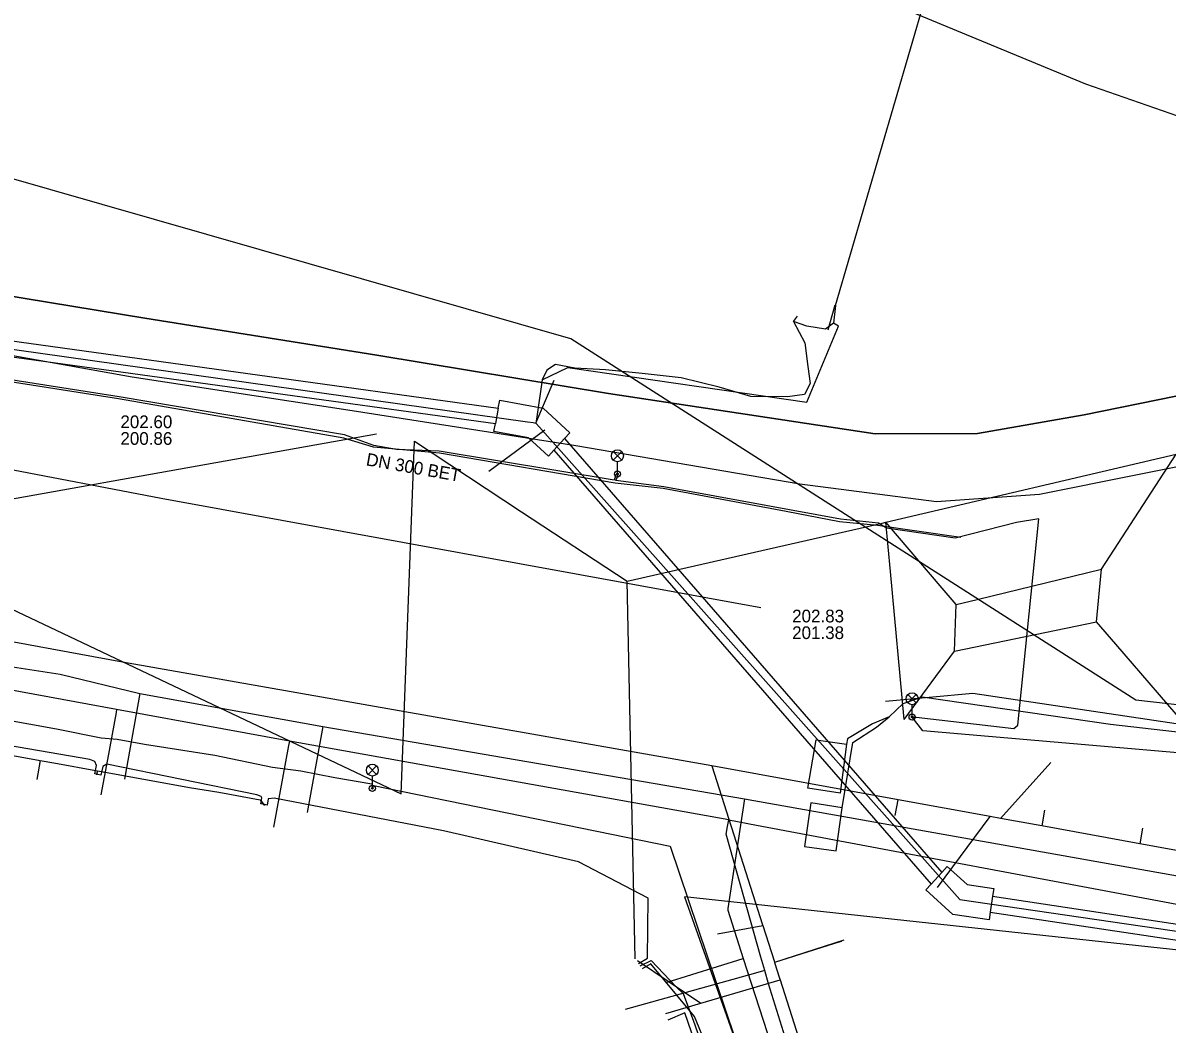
# Model space of a CAD drawing. Extents: x -596228 to -595156, y -1161235 to -1159373.
# Drawn here: x -595841.1 to -595769, y -1160360.2 to -1160297.1 of the extents above; entities that cross this region are included whole.
import ezdxf

# ---------------------------------------------------------------- set-up
doc = ezdxf.new("R2010")
doc.units = 0
for name, color, linetype in [('Vrstva 1', 7, 'Continuous'), ('Vrstva 10', 7, 'Continuous'), ('Vrstva 12', 7, 'Continuous'), ('Vrstva 14', 7, 'Continuous'), ('Vrstva 16', 7, 'Continuous'), ('Vrstva 33', 7, 'Continuous'), ('Vrstva 4', 7, 'Continuous'), ('Vrstva 42', 7, 'Continuous'), ('Vrstva 54', 7, 'Continuous'), ('Vrstva 55', 7, 'Continuous'), ('Vrstva 58', 7, 'Continuous'), ('Vrstva 9', 7, 'Continuous')]:
    doc.layers.add(name, color=color, linetype=linetype)

msp = doc.modelspace()

# ---------------------------------------------------------------- linework, layer by layer
at = {"layer": 'Vrstva 1'}
for p, q in [((-595806.58, -1160316.98), (-595854.43, -1160303.29)), ((-595832.393, -1160327.051), (-595871.84, -1160319.47)), ((-595832.39, -1160327.05), (-595871.84, -1160319.47)), ((-595794.593, -1160333.931), (-595832.39, -1160327.05)), ((-595794.59, -1160333.93), (-595832.39, -1160327.05)), ((-595776.32, -1160343.68), (-595779.499, -1160347.202)), ((-595786.122, -1160347.012), (-595785.943, -1160346.028)), ((-595776.709, -1160346.693), (-595776.888, -1160347.677)), ((-595783.46, -1160351.56), (-595780.139, -1160347.085)), ((-595770.541, -1160347.816), (-595770.72, -1160348.8)), ((-595797.33, -1160354.48), (-595794.477, -1160353.949)), ((-595797.328, -1160354.476), (-595794.48, -1160353.95)), ((-595789.37, -1160354.88), (-595793.729, -1160356.29)), ((-595802.38, -1160356.15), (-595798.38, -1160358.85))]:
    msp.add_line(p, q, dxfattribs=at)
for points in [[(-595760, -1160341), (-595761.123, -1160340.872), (-595770.963, -1160339.746), (-595806.58, -1160316.98)], [(-595765.83, -1160349.69), (-595770.72, -1160348.8), (-595776.888, -1160347.677), (-595779.499, -1160347.202), (-595780.139, -1160347.085), (-595785.943, -1160346.028), (-595797.69, -1160343.89)], [(-595789.506, -1160354.95), (-595789.956, -1160355.081), (-595793.729, -1160356.29)]]:
    msp.add_lwpolyline(points, dxfattribs=at)
at = {"layer": 'Vrstva 10'}
for p, q in [((-595887.89, -1160310.72), (-595811.15, -1160321.35)), ((-595887.89, -1160310.72), (-595811.15, -1160321.35)), ((-595888.05, -1160311.71), (-595811.33, -1160322.33)), ((-595888.05, -1160311.71), (-595811.33, -1160322.33)), ((-595811.15, -1160321.35), (-595811.33, -1160322.33)), ((-595811.15, -1160321.35), (-595811.33, -1160322.33)), ((-595806.97, -1160323.27), (-595807.64, -1160324.01)), ((-595806.97, -1160323.27), (-595807.64, -1160324.01)), ((-595806.97, -1160323.27), (-595783.19, -1160350.6)), ((-595806.97, -1160323.27), (-595783.19, -1160350.6)), ((-595807.64, -1160324.01), (-595783.86, -1160351.34)), ((-595807.64, -1160324.01), (-595783.86, -1160351.34)), ((-595783.19, -1160350.6), (-595783.86, -1160351.34)), ((-595783.19, -1160350.6), (-595783.86, -1160351.34)), ((-595779.99, -1160352.11), (-595780.14, -1160353.1)), ((-595779.99, -1160352.11), (-595780.14, -1160353.1)), ((-595779.99, -1160352.11), (-595735.23, -1160358.87)), ((-595779.99, -1160352.11), (-595735.23, -1160358.87)), ((-595780.14, -1160353.1), (-595735.26, -1160359.88)), ((-595780.14, -1160353.1), (-595735.26, -1160359.88))]:
    msp.add_line(p, q, dxfattribs=at)
for points in [[(-595811.15, -1160321.35), (-595811.06, -1160320.86), (-595808.32, -1160321.36), (-595806.63, -1160322.9), (-595806.97, -1160323.27)], [(-595811.15, -1160321.35), (-595811.06, -1160320.86), (-595808.32, -1160321.36), (-595806.63, -1160322.9), (-595806.97, -1160323.27)], [(-595807.64, -1160324.01), (-595807.98, -1160324.38), (-595809.25, -1160323.23), (-595811.42, -1160322.82), (-595811.33, -1160322.33)], [(-595807.64, -1160324.01), (-595807.98, -1160324.38), (-595809.25, -1160323.23), (-595811.42, -1160322.82), (-595811.33, -1160322.33)], [(-595783.19, -1160350.6), (-595782.85, -1160350.23), (-595781.6, -1160351.37), (-595779.92, -1160351.61), (-595779.99, -1160352.11)], [(-595783.19, -1160350.6), (-595782.85, -1160350.23), (-595781.6, -1160351.37), (-595779.92, -1160351.61), (-595779.99, -1160352.11)], [(-595780.14, -1160353.1), (-595780.21, -1160353.59), (-595782.49, -1160353.26), (-595784.2, -1160351.71), (-595783.86, -1160351.34)], [(-595780.14, -1160353.1), (-595780.21, -1160353.59), (-595782.49, -1160353.26), (-595784.2, -1160351.71), (-595783.86, -1160351.34)]]:
    msp.add_lwpolyline(points, dxfattribs=at)
at = {"layer": 'Vrstva 12'}
for p, q in [((-595789.89, -1160314.88), (-595777.93, -1160273.94)), ((-595790.362, -1160316.409), (-595789.904, -1160314.845)), ((-595789.89, -1160314.88), (-595790.02, -1160315.99)), ((-595792.54, -1160315.89), (-595792.28, -1160315.55)), ((-595789.7, -1160316.19), (-595790.02, -1160315.99)), ((-595808.78, -1160322.29), (-595807.62, -1160319.58)), ((-595811.75, -1160325.33), (-595808.21, -1160322.72)), ((-595809.314, -1160322.217), (-595808.956, -1160322.265)), ((-595808.956, -1160322.265), (-595808.78, -1160322.29)), ((-595808.78, -1160322.29), (-595808.547, -1160322.55)), ((-595840.02, -1160343.56), (-595840.06, -1160343.77)), ((-595836.4, -1160344.21), (-595836.47, -1160344.42))]:
    msp.add_line(p, q, dxfattribs=at)
for points in [[(-595930.09, -1160299.24), (-595889.94, -1160310.85), (-595809.314, -1160322.217)], [(-595792.54, -1160315.89), (-595791.83, -1160317.23), (-595791.63, -1160318.73), (-595791.48, -1160319.81), (-595791.84, -1160320.5), (-595792.92, -1160320.64), (-595795.22, -1160320.62), (-595797.23, -1160320.04), (-595799.61, -1160319.44), (-595802.07, -1160319.16), (-595804.38, -1160318.93), (-595806.33, -1160318.84), (-595807.54, -1160318.61), (-595808.09, -1160318.97), (-595808.38, -1160319.56)], [(-595808.38, -1160319.56), (-595806.76, -1160318.8), (-595791.7, -1160320.98), (-595789.7, -1160316.19)], [(-595790.02, -1160315.99), (-595790.52, -1160316.37), (-595791.69, -1160316.19), (-595792.54, -1160315.89)], [(-595808.38, -1160319.56), (-595808.719, -1160321.896), (-595808.78, -1160322.29)], [(-595808.547, -1160322.55), (-595782.05, -1160352.31), (-595733.28, -1160359.44)], [(-595858.15, -1160340.11), (-595856.31, -1160340.7), (-595850.28, -1160341.68), (-595840.02, -1160343.56)], [(-595840.02, -1160343.56), (-595839.17, -1160343.71), (-595836.4, -1160344.21)], [(-595836.4, -1160344.21), (-595835.57, -1160344.36), (-595830.62, -1160345.26), (-595828.76, -1160345.54), (-595826.15, -1160346.04), (-595825.94, -1160346.32)], [(-595797.48, -1160364.09), (-595797.91, -1160363.72), (-595799.39, -1160359.46), (-595800.47, -1160359.91)]]:
    msp.add_lwpolyline(points, dxfattribs=at)
at = {"layer": 'Vrstva 14'}
for p, q in [((-595796.71, -1160347.71), (-595796.62, -1160347.3)), ((-595796.62, -1160347.3), (-595794.88, -1160347.62)), ((-595794.88, -1160347.62), (-595751.09, -1160355.87))]:
    msp.add_line(p, q, dxfattribs=at)
for points in [[(-595796.62, -1160347.3), (-595824.314, -1160342.334), (-595828.542, -1160341.559), (-595835.203, -1160340.338), (-595848.129, -1160337.968), (-595856.324, -1160336.466), (-595859.13, -1160335.952), (-595871.786, -1160333.632), (-595881.289, -1160331.89), (-595903.564, -1160327.806)], [(-595835.203, -1160340.338), (-595835.24, -1160340.535), (-595835.782, -1160343.496), (-595836.19, -1160345.721)], [(-595824.314, -1160342.334), (-595824.366, -1160342.617), (-595825.307, -1160347.751)], [(-595779.99, -1160397.64), (-595780.18, -1160397.54), (-595780.72, -1160397.28), (-595782.55, -1160395.85), (-595783.69, -1160391.99), (-595785.31, -1160386.2), (-595787, -1160380.5), (-595787.925, -1160377.543), (-595788.79, -1160374.78), (-595790.115, -1160370.513), (-595792.33, -1160363.34), (-595794.11, -1160357.63), (-595794.351, -1160356.78), (-595794.59, -1160355.94), (-595796.79, -1160348.19), (-595796.71, -1160347.71)], [(-595794.351, -1160356.78), (-595794.495, -1160356.821), (-595795.457, -1160357.095), (-595803.151, -1160359.249)]]:
    msp.add_lwpolyline(points, dxfattribs=at)
at = {"layer": 'Vrstva 16'}
for p, q in [((-595833.73, -1160339.33), (-595834.7, -1160344.74)), ((-595822.21, -1160341.41), (-595823.19, -1160346.82)), ((-595800.57, -1160357.54), (-595795.71, -1160356.02))]:
    msp.add_line(p, q, dxfattribs=at)
for points in [[(-595846.15, -1160336.98), (-595838.77, -1160338.11), (-595833.73, -1160339.33), (-595822.21, -1160341.41), (-595795.62, -1160345.96), (-595752.4, -1160353.65), (-595705.45, -1160352.2), (-595699.2, -1160353.46), (-595687.59, -1160351.18), (-595687.183, -1160350.999), (-595649.82, -1160334.37), (-595637.18, -1160329.71), (-595632.58, -1160328.19), (-595631.22, -1160327.8), (-595629.94, -1160327.43), (-595628.67, -1160326.89), (-595623.45, -1160328.11), (-595616.75, -1160330.26), (-595616.2, -1160330.11), (-595541.13, -1160299.69), (-595536.93, -1160298.59)], [(-595795.62, -1160345.96), (-595796.67, -1160352.88), (-595796.68, -1160352.98)], [(-595796.68, -1160352.98), (-595795.71, -1160356.02), (-595792.44, -1160366.14), (-595787.82, -1160380.41), (-595782.96, -1160397.81)]]:
    msp.add_lwpolyline(points, dxfattribs=at)
at = {"layer": 'Vrstva 33'}
for p, q in [((-595803.9, -1160324.091), (-595803.37, -1160324.621)), ((-595803.9, -1160324.621), (-595803.37, -1160324.091)), ((-595803.635, -1160325.506), (-595803.635, -1160324.731)), ((-595785.329, -1160339.397), (-595784.799, -1160339.927)), ((-595785.329, -1160339.927), (-595784.799, -1160339.397)), ((-595785.064, -1160340.812), (-595785.064, -1160340.037)), ((-595819.35, -1160343.896), (-595818.82, -1160344.426)), ((-595819.35, -1160344.426), (-595818.82, -1160343.896)), ((-595819.085, -1160345.311), (-595819.085, -1160344.536))]:
    msp.add_line(p, q, dxfattribs=at)
for centre, radius in [((-595803.635, -1160324.356), 0.375), ((-595803.635, -1160325.506), 0.19), ((-595803.635, -1160325.506), 0.05), ((-595785.064, -1160339.662), 0.375), ((-595785.064, -1160340.812), 0.19), ((-595785.064, -1160340.812), 0.05), ((-595819.085, -1160344.161), 0.375), ((-595819.085, -1160345.311), 0.19), ((-595819.085, -1160345.311), 0.05)]:
    msp.add_circle(centre, radius, dxfattribs=at)
at = {"layer": 'Vrstva 42'}
for points in [[(-595847.13, -1160313.44), (-595833.42, -1160315.69), (-595818.81, -1160318.02), (-595804.19, -1160320.42), (-595787.39, -1160322.98), (-595780.95, -1160322.96), (-595774.21, -1160321.77), (-595762.67, -1160319.43), (-595752.552, -1160316.857), (-595741.43, -1160313.41), (-595738.39, -1160315.27), (-595735.13, -1160315.87), (-595731.62, -1160314.9), (-595724.29, -1160311.87), (-595722.868, -1160311.197), (-595714.82, -1160307.83), (-595703.02, -1160300.19), (-595693.78, -1160291.95), (-595681.58, -1160277.83), (-595677.955, -1160273.423), (-595678.45, -1160273.05)], [(-595847.13, -1160313.44), (-595833.42, -1160315.69), (-595818.81, -1160318.02), (-595804.19, -1160320.42), (-595787.39, -1160322.98), (-595780.95, -1160322.96), (-595774.21, -1160321.77), (-595762.67, -1160319.43), (-595752.552, -1160316.857), (-595741.43, -1160313.41), (-595738.39, -1160315.27), (-595735.13, -1160315.87), (-595731.62, -1160314.9), (-595724.29, -1160311.87), (-595722.868, -1160311.197), (-595714.82, -1160307.83), (-595703.02, -1160300.19), (-595693.78, -1160291.95), (-595681.58, -1160277.83), (-595677.955, -1160273.423), (-595678.45, -1160273.05)], [(-595678.45, -1160273.05), (-595677.955, -1160273.423), (-595681.58, -1160277.83), (-595693.78, -1160291.95), (-595703.02, -1160300.19), (-595714.82, -1160307.83), (-595722.868, -1160311.197), (-595724.29, -1160311.87), (-595731.62, -1160314.9), (-595735.13, -1160315.87), (-595738.39, -1160315.27), (-595741.43, -1160313.41), (-595752.552, -1160316.857), (-595762.67, -1160319.43), (-595774.21, -1160321.77), (-595780.95, -1160322.96), (-595787.39, -1160322.98), (-595804.19, -1160320.42), (-595818.81, -1160318.02), (-595833.42, -1160315.69), (-595847.13, -1160313.44)], [(-595847.13, -1160313.44), (-595833.42, -1160315.69), (-595818.81, -1160318.02), (-595804.19, -1160320.42), (-595787.39, -1160322.98), (-595780.95, -1160322.96), (-595774.21, -1160321.77), (-595762.67, -1160319.43), (-595752.552, -1160316.857), (-595741.43, -1160313.41), (-595738.39, -1160315.27), (-595735.13, -1160315.87), (-595731.62, -1160314.9), (-595724.29, -1160311.87), (-595722.868, -1160311.197), (-595714.82, -1160307.83), (-595703.02, -1160300.19), (-595693.78, -1160291.95), (-595681.58, -1160277.83), (-595677.955, -1160273.423)], [(-595847.13, -1160313.44), (-595833.42, -1160315.69), (-595818.81, -1160318.02), (-595804.19, -1160320.42), (-595787.39, -1160322.98), (-595780.95, -1160322.96), (-595774.21, -1160321.77), (-595762.67, -1160319.43), (-595752.552, -1160316.857), (-595741.43, -1160313.41), (-595738.39, -1160315.27), (-595735.13, -1160315.87), (-595731.62, -1160314.9), (-595724.29, -1160311.87), (-595722.868, -1160311.197), (-595714.82, -1160307.83), (-595703.02, -1160300.19), (-595693.78, -1160291.95), (-595681.58, -1160277.83), (-595677.955, -1160273.423)], [(-595847.13, -1160313.44), (-595833.42, -1160315.69), (-595818.81, -1160318.02), (-595804.19, -1160320.42), (-595787.39, -1160322.98), (-595780.95, -1160322.96), (-595774.21, -1160321.77), (-595762.67, -1160319.43), (-595752.552, -1160316.857), (-595741.43, -1160313.41), (-595738.39, -1160315.27), (-595735.13, -1160315.87), (-595731.62, -1160314.9), (-595724.29, -1160311.87), (-595722.868, -1160311.197), (-595714.82, -1160307.83), (-595703.02, -1160300.19), (-595693.78, -1160291.95), (-595681.58, -1160277.83), (-595677.955, -1160273.423)], [(-595847.13, -1160313.44), (-595833.42, -1160315.69), (-595818.81, -1160318.02), (-595804.19, -1160320.42), (-595787.39, -1160322.98), (-595780.95, -1160322.96), (-595774.21, -1160321.77), (-595762.67, -1160319.43), (-595752.552, -1160316.857), (-595741.43, -1160313.41), (-595738.39, -1160315.27), (-595735.13, -1160315.87), (-595731.62, -1160314.9), (-595724.29, -1160311.87), (-595722.868, -1160311.197), (-595714.82, -1160307.83), (-595703.02, -1160300.19), (-595693.78, -1160291.95), (-595681.58, -1160277.83), (-595677.955, -1160273.423)], [(-595895.894, -1160304.949), (-595895.931, -1160305.565), (-595896.41, -1160308.706), (-595893.65, -1160309.078), (-595880.587, -1160311.231), (-595867.748, -1160313.527), (-595860.217, -1160314.981), (-595847.991, -1160316.922), (-595834.216, -1160319.371), (-595820.364, -1160321.5), (-595806.264, -1160323.708), (-595792.142, -1160326.114), (-595783.529, -1160327.233), (-595777.032, -1160326.773), (-595764.779, -1160324.315), (-595754.282, -1160321.569), (-595753.606, -1160323.921), (-595750.637, -1160332.868), (-595750.632, -1160333.38), (-595740.462, -1160333.548), (-595739.673, -1160332.748), (-595739.749, -1160331.939)], [(-595786.51, -1160340.81), (-595785.62, -1160339.97), (-595784.43, -1160339.54), (-595772.55, -1160341.27), (-595759.72, -1160342.74), (-595753.29, -1160343.01), (-595746.78, -1160343.15), (-595744.71, -1160344.54), (-595744.9, -1160333.41), (-595739.78, -1160333.4), (-595731.42, -1160332.67), (-595721.4, -1160331.47), (-595721.02, -1160331.89), (-595720.93, -1160332.76), (-595720.32, -1160336.61), (-595718.38, -1160336.3), (-595717.93, -1160338.83), (-595719.88, -1160339.16), (-595720.32, -1160336.61)], [(-595756.32, -1160342.9), (-595757.1, -1160342.84), (-595759.12, -1160342.98), (-595766.45, -1160341.54), (-595781.24, -1160339.33), (-595786.74, -1160339.83)], [(-595789.47, -1160346.54), (-595791.44, -1160346.22), (-595791.85, -1160348.97), (-595789.86, -1160349.24), (-595789.47, -1160346.54), (-595788.79, -1160342.41), (-595787.31, -1160341.45), (-595786.51, -1160340.81), (-595787.57, -1160341.25), (-595789.13, -1160342.19), (-595789.19, -1160342.53), (-595789.6, -1160345.62), (-595791.63, -1160345.3), (-595791.12, -1160342.26), (-595789.19, -1160342.53)], [(-595802.315, -1160356.348), (-595801.748, -1160356.007), (-595801.706, -1160352.231), (-595806.091, -1160349.948), (-595814.606, -1160347.981), (-595825.263, -1160345.929), (-595825.632, -1160345.967), (-595825.653, -1160345.979), (-595825.707, -1160346.367), (-595825.893, -1160346.33), (-595826.107, -1160346.291), (-595826.046, -1160345.903), (-595826.096, -1160345.815), (-595826.364, -1160345.707), (-595835.813, -1160343.79), (-595836.08, -1160343.929), (-595836.193, -1160344.469), (-595836.392, -1160344.434), (-595836.583, -1160344.396), (-595836.47, -1160343.865), (-595836.579, -1160343.616), (-595836.883, -1160343.496), (-595845.341, -1160342.033)], [(-595802.213, -1160356.494), (-595801.501, -1160356.155), (-595799.925, -1160357.815), (-595799.472, -1160358.259)], [(-595788.218, -1160395.186), (-595787.922, -1160394.034), (-595788.748, -1160391.473), (-595790.389, -1160386.386), (-595791.885, -1160381.611), (-595792.977, -1160378.739), (-595793.48, -1160376.711), (-595793.46, -1160376.649), (-595793.33, -1160376.236), (-595793.283, -1160375.424), (-595794.728, -1160370.765), (-595796.979, -1160363.921), (-595797.998, -1160361.576), (-595798.784, -1160359.683), (-595799.078, -1160359.328), (-595801.526, -1160356.363), (-595802.086, -1160356.676)], [(-595793.939, -1160376.733), (-595794.104, -1160376.213), (-595793.629, -1160376.048), (-595793.665, -1160375.597), (-595795.975, -1160367.94), (-595796.283, -1160367.628), (-595796.85, -1160367.774), (-595796.901, -1160367.605), (-595796.969, -1160367.392), (-595796.392, -1160367.161), (-595796.411, -1160366.856), (-595798.853, -1160359.936), (-595799.078, -1160359.328), (-595799.472, -1160358.259)]]:
    msp.add_lwpolyline(points, dxfattribs=at)
at = {"layer": 'Vrstva 54'}
for p, q in [((-595818.83, -1160322.99), (-595829.53, -1160324.9)), ((-595816.56, -1160326.77), (-595816.43, -1160323.44)), ((-595816.43, -1160323.44), (-595809.68, -1160327.88)), ((-595786.71, -1160328.54), (-595768.42, -1160324.25)), ((-595773.12, -1160331.49), (-595768.42, -1160324.25)), ((-595829.53, -1160324.9), (-595847.48, -1160328.1)), ((-595817.27, -1160345.66), (-595816.56, -1160326.77)), ((-595809.68, -1160327.88), (-595803.02, -1160332.26)), ((-595794.54, -1160330.33), (-595786.95, -1160328.59)), ((-595786.95, -1160328.59), (-595786.71, -1160328.54)), ((-595786.42, -1160331.64), (-595786.71, -1160328.54)), ((-595783.17, -1160332.69), (-595786.71, -1160328.54)), ((-595803.02, -1160332.26), (-595794.54, -1160330.33)), ((-595848.051, -1160331.075), (-595817.27, -1160345.66)), ((-595780.96, -1160333.41), (-595773.12, -1160331.49)), ((-595773.444, -1160334.821), (-595773.12, -1160331.49)), ((-595802.51, -1160356.06), (-595803.02, -1160332.26)), ((-595785.56, -1160340.96), (-595786.42, -1160331.64)), ((-595782.28, -1160333.73), (-595783.17, -1160332.69)), ((-595782.402, -1160336.659), (-595782.28, -1160333.73)), ((-595782.28, -1160333.73), (-595780.96, -1160333.41)), ((-595775.37, -1160335.22), (-595773.444, -1160334.821)), ((-595772.23, -1160336.23), (-595773.444, -1160334.821)), ((-595782.402, -1160336.659), (-595775.37, -1160335.22)), ((-595766.53, -1160342.85), (-595772.23, -1160336.23)), ((-595785.56, -1160340.96), (-595782.402, -1160336.659))]:
    msp.add_line(p, q, dxfattribs=at)
at = {"layer": 'Vrstva 55'}
for points in [[(-595785.07, -1160340.83), (-595784.8, -1160340.83), (-595778.65, -1160341.54), (-595778.39, -1160341.33), (-595777.08, -1160328.32), (-595778.48, -1160328.56), (-595782.35, -1160329.55), (-595786.68, -1160328.91), (-595787.19, -1160328.6), (-595789.58, -1160328.34), (-595800.71, -1160326.31), (-595803.729, -1160325.918), (-595803.64, -1160325.675), (-595803.622, -1160325.626), (-595803.64, -1160325.5), (-595803.735, -1160325.585), (-595803.85, -1160325.9), (-595814.88, -1160324.07), (-595817.56, -1160323.95), (-595818.99, -1160323.7), (-595820.85, -1160323.04), (-595835.05, -1160320.63), (-595844.03, -1160319.24)], [(-595845.76, -1160340.33), (-595839, -1160341.56), (-595836.18, -1160342.12), (-595835.17, -1160342.22), (-595833.44, -1160342.52), (-595829.02, -1160343.21), (-595825.38, -1160343.97), (-595823.6, -1160344.21), (-595821.45, -1160344.62), (-595819.11, -1160345.03), (-595819.059, -1160345.347)], [(-595739.873, -1160372.217), (-595738.96, -1160372.66), (-595734.72, -1160369.55), (-595737.66, -1160362.94), (-595741.68, -1160359.18), (-595745.95, -1160355.16), (-595747.67, -1160343.9), (-595750.378, -1160344.227), (-595760.77, -1160343.73), (-595784.389, -1160341.684), (-595785.07, -1160340.83)], [(-595819.059, -1160345.347), (-595819.009, -1160345.12), (-595800.32, -1160348.95), (-595795.678, -1160362.699), (-595798.673, -1160363.335)], [(-595739.802, -1160372.295), (-595739.778, -1160371.847), (-595735.46, -1160369.37), (-595737.66, -1160362.94), (-595741.43, -1160359.43), (-595748.2, -1160357.67), (-595799.41, -1160352.15), (-595795.678, -1160362.699), (-595798.673, -1160363.335)]]:
    msp.add_lwpolyline(points, dxfattribs=at)
at = {"layer": 'Vrstva 58'}
for p, q in [((-595840.02, -1160343.56), (-595840.23, -1160344.76)), ((-595836.4, -1160344.21), (-595836.48, -1160344.45))]:
    msp.add_line(p, q, dxfattribs=at)
for points in [[(-595782, -1160329.5), (-595787.24, -1160328.74), (-595789.63, -1160328.51), (-595793.01, -1160327.87), (-595800.76, -1160326.42), (-595803.78, -1160326.07), (-595814.86, -1160324.18), (-595819.01, -1160323.81), (-595820.88, -1160323.24), (-595835.09, -1160320.76), (-595844.21, -1160319.34)], [(-595858.15, -1160340.11), (-595856.31, -1160340.7), (-595850.28, -1160341.68), (-595840.02, -1160343.56)], [(-595840.02, -1160343.56), (-595839.17, -1160343.71), (-595836.4, -1160344.21)], [(-595836.4, -1160344.21), (-595835.57, -1160344.36), (-595830.62, -1160345.26), (-595828.76, -1160345.54), (-595826.15, -1160346.04), (-595825.89, -1160346.39)]]:
    msp.add_lwpolyline(points, dxfattribs=at)
at = {"layer": 'Vrstva 9'}
for p, q in [((-595793.24, -1160292.98), (-595774.127, -1160300.914)), ((-595774.127, -1160300.914), (-595743.039, -1160311.769)), ((-595834.84, -1160337.35), (-595874.28, -1160330.14)), ((-595797.69, -1160343.89), (-595834.84, -1160337.35))]:
    msp.add_line(p, q, dxfattribs=at)
for points in [[(-595797.69, -1160343.89), (-595794.489, -1160353.911), (-595794.477, -1160353.949), (-595793.763, -1160356.183), (-595793.729, -1160356.29), (-595793.416, -1160357.267), (-595793.383, -1160357.371), (-595791.929, -1160361.925), (-595791.841, -1160362.2), (-595788.946, -1160371.261), (-595788.902, -1160371.4), (-595786.349, -1160379.39), (-595786.301, -1160379.54), (-595785.943, -1160380.664), (-595785.906, -1160380.779), (-595784.518, -1160385.123), (-595784.478, -1160385.249), (-595782.65, -1160390.97)], [(-595800.59, -1160359.5), (-595798.38, -1160358.85), (-595793.383, -1160357.371)]]:
    msp.add_lwpolyline(points, dxfattribs=at)

# ---------------------------------------------------------------- texts
at = {"layer": 'Vrstva 4'}
for s, p in [('202.60', (-595834.965, -1160322.614)), ('200.86', (-595834.965, -1160323.664)), ('202.83', (-595792.625, -1160334.851)), ('201.38', (-595792.625, -1160335.901))]:
    msp.add_text(s, height=0.8, dxfattribs=at).set_placement(p)
msp.add_text('DN 300 BET', height=0.8, rotation=350, dxfattribs=at).set_placement((-595819.521, -1160324.952))

doc.saveas('drawing.dxf')
